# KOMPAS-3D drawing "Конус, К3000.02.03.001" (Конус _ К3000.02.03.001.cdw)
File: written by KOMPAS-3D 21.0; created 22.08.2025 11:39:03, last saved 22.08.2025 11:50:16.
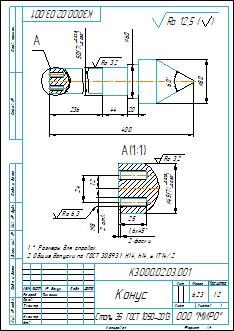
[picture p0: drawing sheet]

Sheet 1: A4, portrait

Document properties: Автор: Lutik; Полное имя файла: C:\Users\Lutik\YandexDisk\Документы\Новая папка\Бабка задняя\2D\Опора_К3000.02.03.000\Конус _ К3000.02.03.001.cdw; Знак неуказанной шероховатости: 4; Параметр неуказанной шероховатости: Ra 12,5; Масса: 6.226632

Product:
- Part/product: Конус  | designation К3000.02.03.001
    Материал: Сталь 35  ГОСТ 1050-2013 (density 7826 kg/m3)
    Масса: 6.226632

Title block, sheet 1: Наименование: Конус; designation: К3000.02.03.001; Материал: Сталь 35  ГОСТ 1050-2013; Масса: 6,23; Количество листов документа: 1; organisation: ООО "МИРО"; Форматы листов документа: A4; Разработал: Тимонин

Views: Вид 1, Местный разрез 1, Сверху, Выносной элемент 2, Выносной элемент А, Выносной элемент
Referenced files in C:\Users\Lutik\YandexDisk\Документы\Новая папка\Бабка задняя\3D\: Конус.m3d
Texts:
  Ra 3,2
  Ra 6,3
  Ra 12,5
  Ra 12,5 ( )
  К3000.02.03.001 Конус
Dimensions and other numbers on the sheet: 80; 400; 60; 50; 236; 44; 20; 12; 24; 8; 2 отв.; 1,6; 2 фаски; 25; 45; 5; 1:2; 1; 6,23

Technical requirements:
  * Размеры для справок.
  Общие допуски по ГОСТ 30893.1: Н14, h14, ± IT14/2.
